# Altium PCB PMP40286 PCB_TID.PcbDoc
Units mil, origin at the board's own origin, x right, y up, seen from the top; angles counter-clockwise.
Board outline 2165.35 x 1574.8 mil, 4 copper layers (Top Layer, Signal Layer 1, Signal Layer 2, Bottom Layer), stack 79.834 mil thick; 40 components, 23 nets, 193 pads, 240 vias.
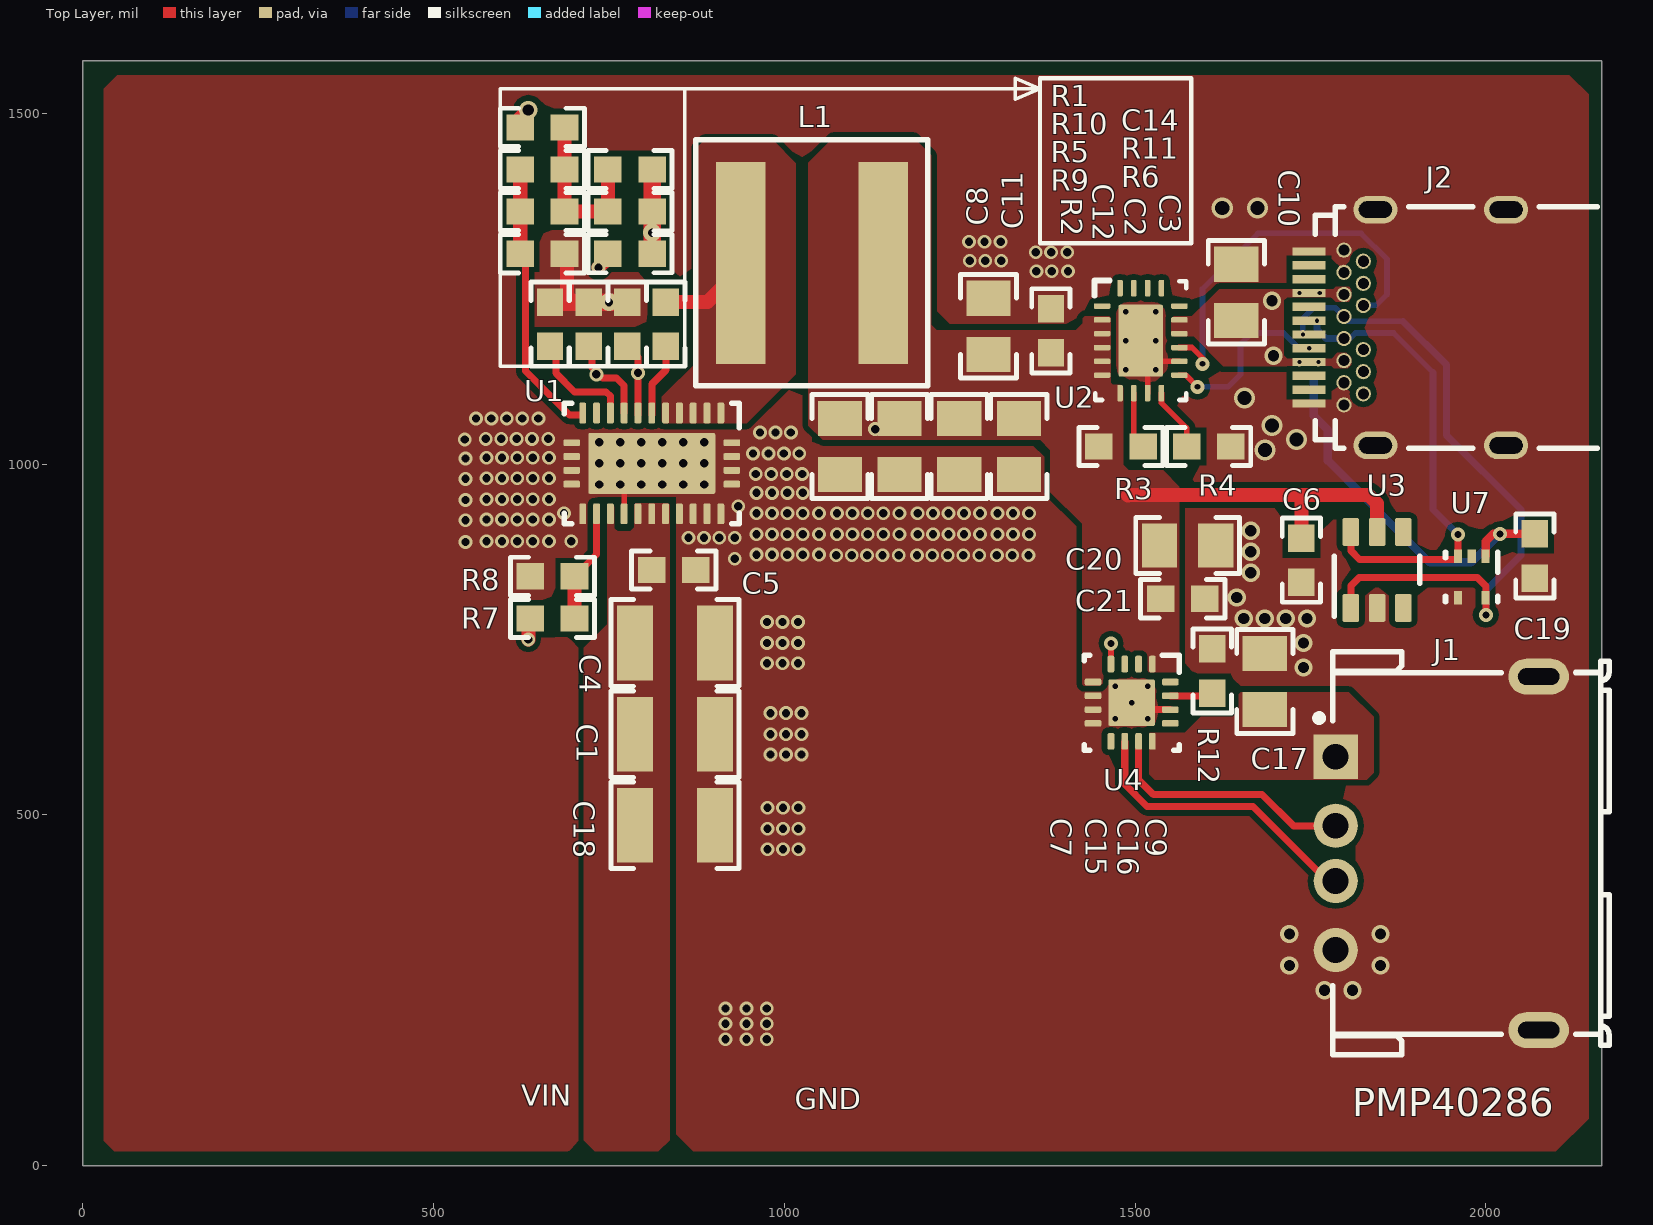
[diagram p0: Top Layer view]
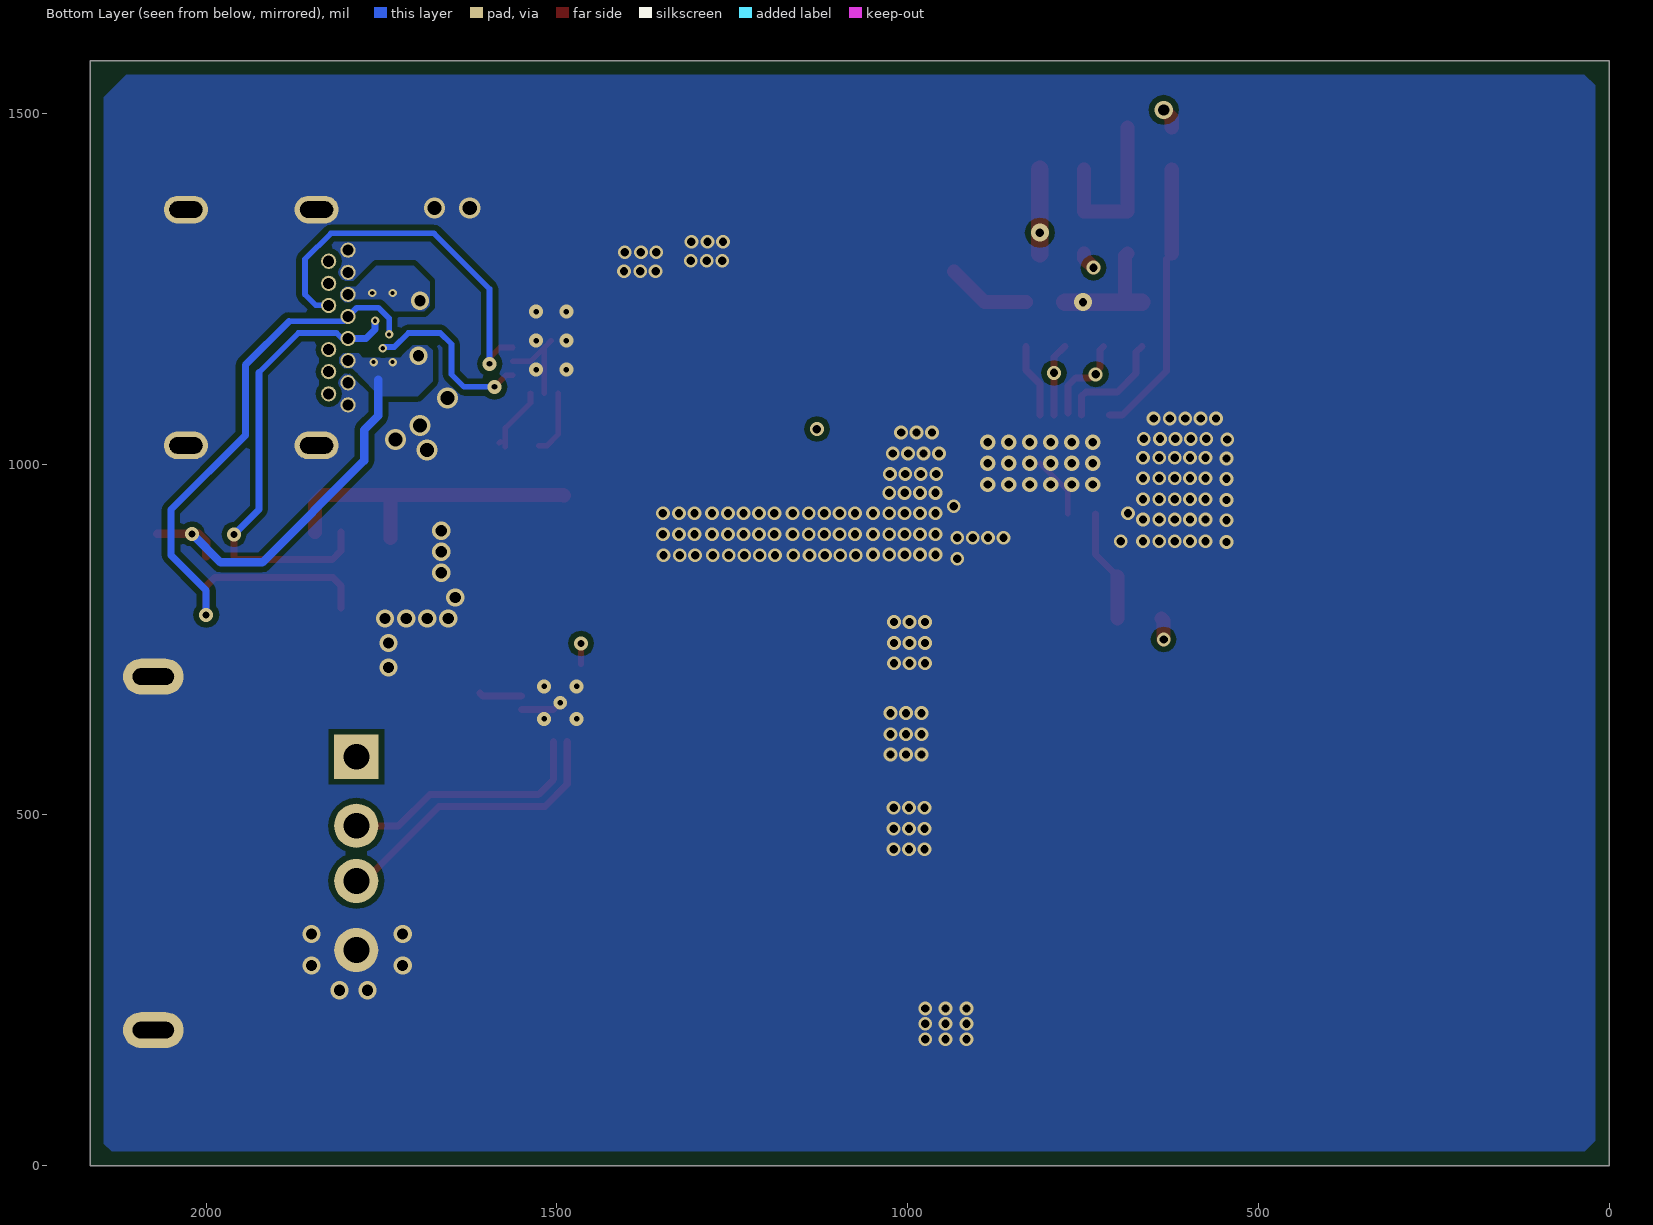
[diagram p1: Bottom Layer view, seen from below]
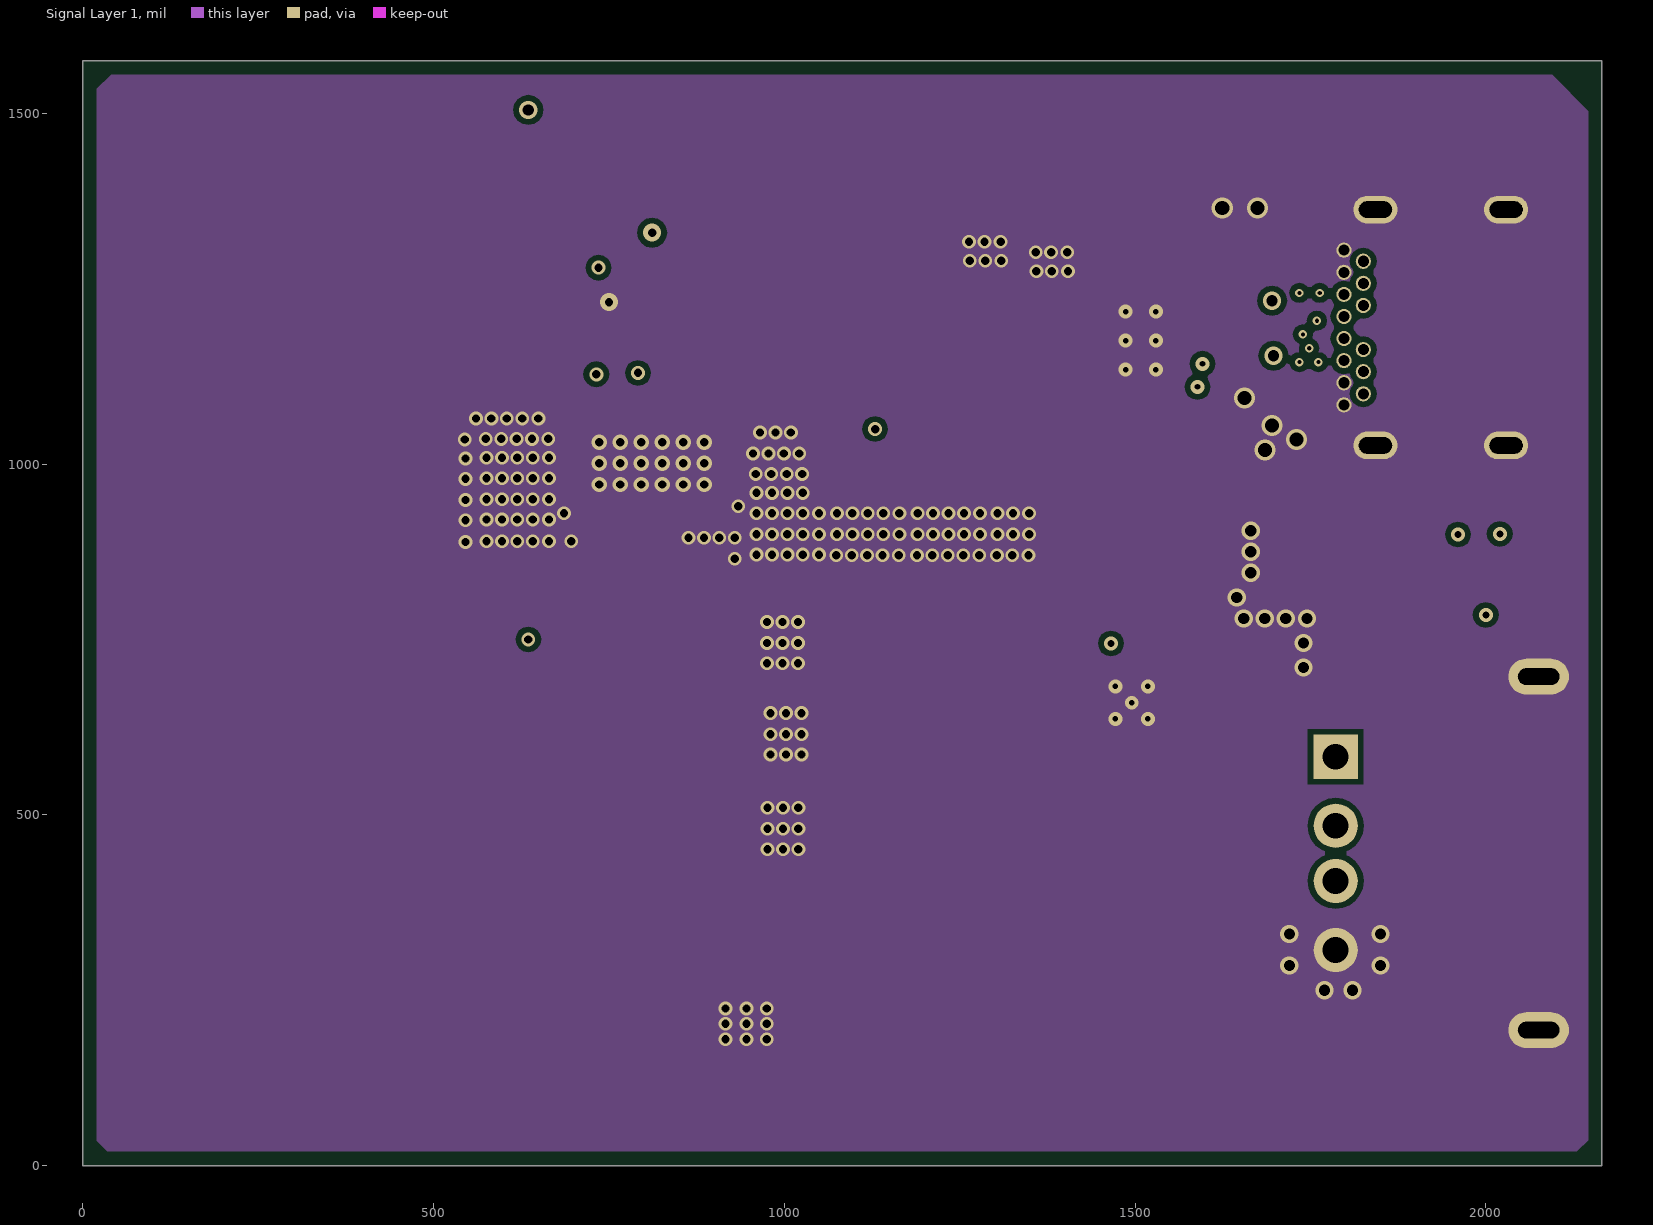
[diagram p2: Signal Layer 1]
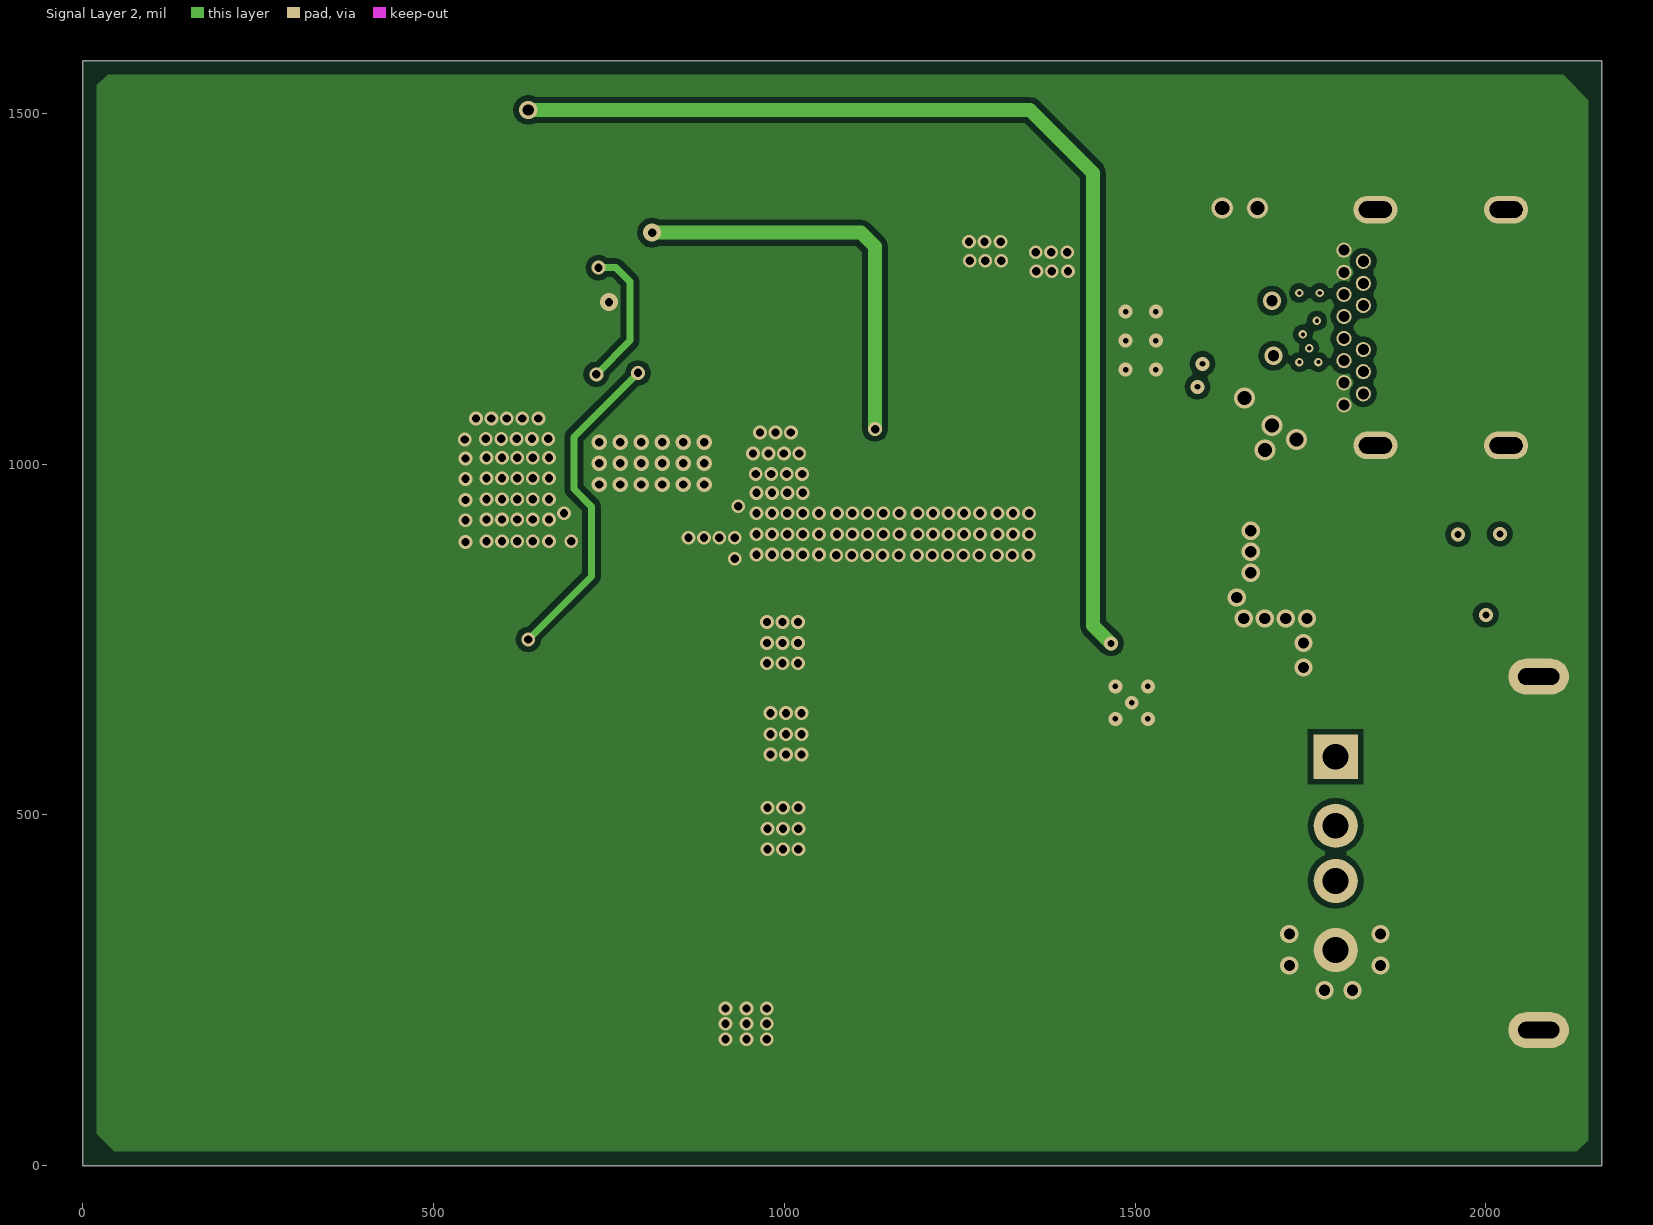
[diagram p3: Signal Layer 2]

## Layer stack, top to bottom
Top Solder: solder mask 0.4, Solder Resist, Dk 3.5
Top Layer: signal copper 1.4
Dielectric1: core 59.2, FR-4, Dk 4.8
Signal Layer 1: signal copper 1.417
Dielectric 3: prepreg 5, Dk 4.2
Signal Layer 2: signal copper 1.417
Dielectric 2: core 10, Dk 4.2
Bottom Layer: signal copper 1.4
Bottom Solder: solder mask 0.4, Solder Resist, Dk 3.5

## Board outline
0,0 2165.35,0 2165.35,1574.8 0,1574.8

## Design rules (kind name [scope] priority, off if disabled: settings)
AcuteAngle [All] p1: minimum=4.50000000000000E+0001 checktracksonly=FALSE
AssemblyTestPointUsage [All] p1: valid=2
Clearance Clearance_BoardEdge_MountingHoles [OnCopper and InComponentClass('Mounting Holes') vs IsKeepOut] p1: gap=40
Clearance Clearance_BoardEdge_Poly [OnCopper and InPoly vs IsKeepOut] p2: gap=5
Clearance Clearance_BoardEdge [OnCopper and Not InComponentClass('Logo') and not InComponentClass('FiducialMark') and not InRegion(1000,500,4000,800) and Not IsKeepout vs IsKeepOut] p3: gap=5
Clearance Clearance_Poly [InPolygon] p4: gap=8
Clearance [All] p5: gap=6
ComponentClearance ComponentClearance_Logo [All] p1: gap=10 collisioncheckmode=3 verticalgap=10 showdistances=TRUE
ComponentClearance ComponentClearance_ScrewToNut [(HasFootprint('NY PMS 440 0025 PH')) vs (HasFootprint('Keystone_1902C'))] p2: gap=5 collisioncheckmode=3 verticalgap=10 showdistances=FALSE
ComponentClearance ComponentClearance_MountingHoles [InComponentClass('Mounting Holes')] p3: gap=10 collisioncheckmode=3 verticalgap=100000 showdistances=FALSE
ComponentClearance ComponentClearance_SmallPassives [HasFootprint('0201*') or HasFootprint('0402*') or HasFootprint('0508') or HasFootprint('0603*') or HasFootprint('0612') or HasFootprint('0805*') or HasFootprint('0815*') or HasFootprint('0830*') or HasFootprint('1206*') or HasFootprint('1210*') or HasFootprint('1808*') or HasFootprint('1812*') or HasFootprint('1825*') or HasFootprint('2010*') or HasFootprint('2220*') or HasFootprint('2225*') or HasFootprint('2512*') or HasFootprint('2728*') or HasFootprint('3518*') vs HasFootprint('0201*') or HasFootprint('0402*') or HasFootprint('0508') or HasFootprint('0603*') or HasFootprint('0612') or HasFootprint('0805*') or HasFootprint('0815*') or HasFootprint('0830*') or HasFootprint('1206*') or HasFootprint('1210*') or HasFootprint('1808*') or HasFootprint('1812*') or HasFootprint('1825*') or HasFootprint('2010*') or HasFootprint('2220*') or HasFootprint('2225*') or HasFootprint('2512*') or HasFootprint('2728*') or HasFootprint('3518*')] p4: gap=10 collisioncheckmode=3 verticalgap=10 showdistances=FALSE
ComponentClearance ComponentClearance_THtoSMT [IsThruComponent vs IsSMTComponent] p5: gap=10 collisioncheckmode=3 verticalgap=100000 showdistances=FALSE
ComponentClearance ComponentClearance_THtoTH [IsThruComponent vs IsThruComponent] p6: gap=10 collisioncheckmode=3 verticalgap=100000 showdistances=FALSE
ComponentClearance [All] p7: gap=10 collisioncheckmode=3 verticalgap=10 showdistances=FALSE
DiffPairsRouting [All] p1: maxlimit=100 minlimit=10 mostfreqgap=10 toplayer_minwidth=15 toplayer_maxwidth=15 toplayer_prefwidth=15 midlayer1_minwidth=15 midlayer1_maxwidth=15 midlayer1_prefwidth=15 midlayer2_minwidth=15 midlayer2_maxwidth=15 midlayer2_prefwidth=15 bottomlayer_minwidth=15 bottomlayer_maxwidth=15 bottomlayer_prefwidth=15 maxuncoupledlength=1000
FabricationTestPointUsage TestPointUsage [All] p1: valid=2 allowmultiple=FALSE
FabricationTestpoint Testpoint [All] p1: side=3 testpointundercomponent=TRUE minsize=40 maxsize=100 preferedsize=60 minholesize=0 maxholesize=40 preferedholesize=32 testpointgrid=1 allowsidetop=TRUE allowsidebottom=TRUE usegrid=TRUE gridtolerance=0.01
FanoutControl Fanout_LCC [IsLCC] p1: bgadir=Out bgaviamode=Centered fanoutstyle=Auto fanoutdirection=Alternating viagrid=1 // Fanout_LCC (Default Rule)
FanoutControl Fanout_BGA [IsBGA] p2: bgadir=Out bgaviamode=Centered fanoutstyle=Auto fanoutdirection=Alternating viagrid=1 // Fanout_BGA (Default Rule)
FanoutControl Fanout_Default [All] p4: bgadir=Out bgaviamode=Centered fanoutstyle=Auto fanoutdirection=Alternating viagrid=1 // Fanout_Default (Default Rule)
FanoutControl Fanout_Small [(CompPinCount < 5)] p5: bgadir=Out bgaviamode=Centered fanoutstyle=Auto fanoutdirection=OutThenIn viagrid=1 // Fanout_Small (Default Rule)
HoleSize [All] p1: absolutevalues=TRUE maxlimit=251 minlimit=6 maxpercent=80.000 minpercent=20.000
MinimumAnnularRing [All] p1: minimumring=3
MinimumSolderMaskSliver MinimumSolderMaskSliver_Logo [InComponentClass('Logo') vs InComponentClass('Logo')] p1: minsoldermaskwidth=0.7
MinimumSolderMaskSliver [All] p2: minsoldermaskwidth=0
PlaneConnect [All] p1: planeconnectstyle=Direct reliefexpansion=10 reliefentries=4 reliefconductorwidth=10 reliefairgap=10
PolygonConnect [All] p1: connectstyle=Direct reliefconductorwidth=10 reliefentries=4 polygonreliefangle="90 Angle" airgapwidth=10
RoutingCorners [All] p1: cornerstyle=45-Degree minsetback=10 maxsetback=100
RoutingVias [All] p1: holewidth=16 width=34 viastyle="Through Hole" minholewidth=8 minwidth=16 maxholewidth=40 maxwidth=65
SMDToCorner [All] p1: distance=0
SilkToBoardRegionClearance [Not ((IsComment or IsDesignator) And (Hide <> 'False')) and not InRegion(1000,500,4000,800)] p1:
SilkToSilkClearance [All] p1: silktosilkclearance=0
SilkToSolderMaskClearance SilkscreenOverComponentPads [IsPad] p1: minsilkscreentomaskgap=0 clearancetoexposedcopper=TRUE
SolderMaskExpansion [All] p1: expansion=3
Width [All] p1: maxlimit=100 minlimit=6 preferedwidth=10 checkconnectedcopper=TRUE
14 further rules are at their usual default settings.

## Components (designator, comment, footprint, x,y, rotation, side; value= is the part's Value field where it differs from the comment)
C1 "GRM32ER71H106KA12L" 1210 844.33,614.96 r0 top
C2 "GRM188R61A225KE34D" 0603 775.99,1199.43 r90 top
C3 "GRM188R71A474KA61D" 0603 830.99,1199.43 r90 top
C4 "GRM32ER71H106KA12L" 1210 844.33,744.96 r0 top
C5 "C1608X7R1H474K080AC" 0603 842.33,848.96 r0 top
C6 "06033C104JAT2A" 0603 1737,863 r270 top
C7 "GRM21BR61A476ME15" 0805_HV 1079.33,1024.96 r270 top
C8 "GRM21BR61A476ME15" 0805_HV 1291.11,1196.47 r90 top
C9 "GRM21BR61A476ME15" 0805_HV 1334.33,1024.96 r270 top
C10 "C0805C106K8PACTU" 0805_HV 1644.33,1244.96 r90 top
C11 "C1608X7R1E104K" 0603 1380,1190 r90 top
C12 "C1608X7R1E104K" 0603 720.99,1199.43 r90 top
C14 "C0603C223K5RACTU" 0603 780,1420 r180 top
C15 "GRM21BR61A476ME15" 0805_HV 1164.33,1024.96 r270 top
C16 "GRM21BR61A476ME15" 0805_HV 1249.33,1024.96 r270 top
C17 "GRM219R61A106KE44D" 0805_HV 1685,690 r90 top
C18 "GRM32ER71H106KA12L" 1210 844.33,484.96 r0 top
C19 "06033C104JAT2A" 0603 2070,869 r270 top
C20 "C0805C106K8PACTU" 0805_HV 1575,884 r0 top
C21 "C1608X7R1E104K" 0603 1568,808 r0 top
J1 "614 104 150 121" WURTH_614104150121 1786.05,445.01 r90 top
J2 "632 723 300 011" Wurth_632_723_300_011 2164.76,1194.72 r90 top
L1 "XAL8080-682MEB" XAL8080 1039.33,1286.96 r0 top
R1 "RC0603JR-070RL" 0603 655,1480 r0 top
R2 "" 0603 665.99,1199.43 r270 top
R3 "CRCW060310K0JNEA" 0603 1480,1025 r180 top
R4 "RC0603FR-07100KL" 0603 1605,1025 r180 top
R5 "RC0603FR-0747KL" 0603 655,1360 r0 top
R6 "CRCW06033R00JNEA" 0603 780,1300 r0 top
R7 "CRCW06030000Z0EA" 0603 669.33,779.96 r180 top
R8 "CRCW06030000Z0EA" 0603 669.33,839.96 r180 top
R9 "CRCW060310K0FKEA" 0603 655,1300 r180 top
R10 "RC0603FR-07200KL" 0603 655,1420 r0 top
R11 "RC0603FR-072K1L" 0603 780,1360 r180 top
R12 "RT0603BRD0720KL" 0603 1610,705 r270 top
U1 "LM73606RNPR" RNP0030A 810.99,1000.93 r270 top
U2 "TPS25810-Q1" RVC0020A 1508.1,1176.02 r0 top
U3 "TPS2514AQDBVRQ1" DBV0006A_N 1845,849 r90 top
U4 "TPS2549IRTERQ1" RTE0016C 1495.16,659.84 r270 top
U7 "TPD2E001IDRLRQ1" DRL0005A 1980,839 r270 top

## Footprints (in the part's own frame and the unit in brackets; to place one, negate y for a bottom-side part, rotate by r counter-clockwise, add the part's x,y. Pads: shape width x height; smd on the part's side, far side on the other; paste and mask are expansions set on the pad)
0603 [mm] "0603 from SM-752 data"
  rect 1x0.95 smd: 1(-0.8,0) 2(0.8,0)
  silkscreen extent -1.52,-0.69 1.52,0.69, body extent -0.87,-0.47 0.87,0.47, height 1
0805_HV [mil] "0805 with 30mil clearance between pads"
  rect 50x63 smd: 1(-40,0) 2(40,0)
  silkscreen extent -74,-40 74,40, body extent -43,-29 43,29, height 57
1210 [mm] "1210 from SM-752 data"
  rect 1.3x2.7 smd: 1(-1.45,0) 2(1.45,0)
  silkscreen extent -2.32,-1.57 2.32,1.57, body extent -1.7,-1.35 1.7,1.35, height 1.35
DBV0006A_N [mm] "SOT23, 6-Leads, Body 2.9x1.6mm, Pitch 0.95mm, Lead Span 2.8mm, IPC Medium Density"
  rrect17% 1x0.6 smd: 1(-1.375,0.95) 2(-1.375,0) 3(-1.375,-0.95) 4(1.375,-0.95) 5(1.375,0) 6(1.375,0.95)
  silkscreen extent -1.68,-1.55 0.5,1.55, body extent -1.42,-1.46 1.42,1.46, height 1.12
DRL0005A [mm] "SOTFL, 5-Flat Leads, Body 1.2x1.6x0.6mm, Pitch 0.5mm, TI recommended"
  rect 0.5x0.3 smd: 1(-0.75,0.5) 2(-0.75,0) 3(-0.75,-0.5) 4(0.75,-0.5) 5(0.75,0.5)
  silkscreen extent -0.9,-0.95 0.9,0.95, body extent -0.85,-0.85 0.85,0.85, height 0.62
RNP0030A [mm] "QFN, 30-Leads, Body 6x4mm, Pitch 0.5mm, Thermal Pad 4.6x2.2mm"
  rrect40% 0.75x0.25 smd: 1(-1.825,2.5) 2(-1.825,2) 3(-1.825,1.5) 4(-1.825,1) 5(-1.825,0.5) 6(-1.825,0) 7(-1.825,-0.5) 8(-1.825,-1) 9(-1.825,-1.5) 10(-1.825,-2) 11(-1.825,-2.5) 16(1.825,-2.5) 17(1.825,-2) 18(1.825,-1.5) 19(1.825,-1) 20(1.825,-0.5) 21(1.825,0) 22(1.825,0.5) 23(1.825,1) 24(1.825,1.5) 25(1.825,2) 26(1.825,2.5)
  rrect40% 0.25x0.6 smd: 12(-0.75,-2.9) 13(-0.25,-2.9) 14(0.25,-2.9) 15(0.75,-2.9) 27(0.75,2.9) 28(0.25,2.9) 29(-0.25,2.9) 30(-0.75,2.9)
  rrect5% 2.2x4.6 smd paste-3: 31(0,0)
  rrect50% 0.98x0.96 on Top Paste: 31A(-0.59,1.74) 31A(-0.59,0.58) 31A(-0.59,-0.58) 31A(-0.59,-1.74) 31A(0.59,1.74) 31A(0.59,0.58) 31A(0.59,-0.58) 31A(0.59,-1.74)
  silkscreen extent -2.17,-3.18 2.17,3.18, body extent -2.07,-3.07 2.07,3.07, height 0.81
RTE0016C [mm] "Texas Insturments"
  rrect42% 0.6x0.24 smd: 1(-1.4,0.75) 2(-1.4,0.25) 3(-1.4,-0.25) 4(-1.4,-0.75) 9(1.4,-0.75) 10(1.4,-0.25) 11(1.4,0.25) 12(1.4,0.75)
  rrect42% 0.24x0.6 smd: 5(-0.75,-1.4) 6(-0.25,-1.4) 7(0.25,-1.4) 8(0.75,-1.4) 13(0.75,1.4) 14(0.25,1.4) 15(-0.25,1.4) 16(-0.75,1.4)
  rrect6% 1.55x1.55 on Top Paste: 17(0,0)
  rrect6% 1.68x1.68 smd paste-0.85: 17(0,0)
  silkscreen extent -1.72,-1.73 1.72,1.73, body extent -1.57,-1.57 1.58,1.58, height 0.81
RVC0020A [mm] "TI"
  rrect50% 0.6x0.2 smd: 1(-1.4,1.25) 2(-1.4,0.75) 3(-1.4,0.25) 4(-1.4,-0.25) 5(-1.4,-0.75) 6(-1.4,-1.25) 11(1.4,-1.25) 12(1.4,-0.75) 13(1.4,-0.25) 14(1.4,0.25) 15(1.4,0.75) 16(1.4,1.25)
  rrect50% 0.2x0.6 smd: 7(-0.75,-1.9) 8(-0.25,-1.9) 9(0.25,-1.9) 10(0.75,-1.9) 17(0.75,1.9) 18(0.25,1.9) 19(-0.25,1.9) 20(-0.75,1.9)
  rrect9% 1.47x1.15 on Top Paste: 21(0,-0.675) 21(0,0.675)
  rrect6% 1.6x2.6 smd paste-1: 21(0,0)
  silkscreen extent -1.68,-2.15 1.65,2.18, body extent -1.55,-2.05 1.55,2.05, height 0.8
Wurth_632_723_300_011 [mm] "Connector, Receptacle, USB Type C, R/A"
  rect 0.3x1.2 smd: A1(-2.75,10.58) A2(-2.25,10.58) A3(-1.75,10.58) A4(-1.25,10.58) A5(-0.75,10.58) A6(-0.25,10.58) A7(0.25,10.58) A8(0.75,10.58) A9(1.25,10.58) A10(1.75,10.58) A11(2.25,10.58) A12(2.75,10.58)
  round 0.55 hole 0.4: B1(2.8,9.32) B2(2.4,8.62) B3(1.6,8.62) B4(1.2,9.32) B5(0.8,8.62) B6(0.4,9.32) B7(-0.4,9.32) B8(-0.8,8.62) B9(-1.2,9.32) B10(-1.6,8.62) B11(-2.4,8.62) B12(-2.8,9.32) M1(2,9.32) M2(-2,9.32)
  rrect100% 1x1.6 hole 0.6 slot 1.2 at 90 deg: S1(-4.27,8.18) S2(-4.27,3.45) S3(4.27,3.45) S4(4.27,8.18)
  silkscreen extent -4.37,0.15 4.37,10.36, body extent -4.37,-0.96 4.37,10.83, height 3.07
WURTH_614104150121 [mm] "USB2.0 A, TH"
  rect 1.6x1.6 hole 0.94: 1(3.5,0)
  round 1.6 hole 0.94: 2(1,0) 3(-1,0) 4(-3.5,0)
  oval 1.3x2.2 hole 0.6 slot 1.5 at 90 deg: 5(-6.4,-7.35) 6(6.4,-7.35)
  silkscreen extent -7.3,-9.9 7.3,0.72, body extent -7.3,-9.9 7.3,0.1, height 6.93
XAL8080 [mm] "Coilcraft"
  rect 1.78x7.31 smd: 1(-2.58,0) 2(2.58,0)
  silkscreen extent -4.2,-4.45 4.2,4.45, body extent -4.15,-4.4 4.15,4.4, height 8

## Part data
C1 C4 C18: "CAP, CERM, 10 µF, 50 V, +/- 10%, X7R, 1210"
C2: "CAP, CERM, 2.2 µF, 10 V, +/- 10%, X5R, 0603"
C3: "CAP, CERM, 0.47 µF, 10 V, +/- 10%, X7R, 0603"
C5: "CAP, CERM, 0.47 µF, 50 V, +/- 10%, X7R, 0603"
C6 C19: "CAP, CERM, 0.1 µF, 25 V, +/- 5%, X7R, 0603"
C7 C8 C9 C15 C16: "CAP, CERM, 47 µF, 10 V, +/- 20%, X5R, 0805"
C10 C17 C20: "CAP, CERM, 10 µF, 10 V, +/- 10%, X5R, 0805"
C11 C12 C21: "CAP, CERM, 0.1 µF, 25 V, +/- 10%, X7R, 0603"
C14: "CAP, CERM, 0.022 µF, 50 V, +/- 10%, X7R, 0603"
J1: "Connector, Receptacle, USB Type A, R/A, Bottom Mount TH"
J2: "Connector, Receptacle, USB Type C, R/A"
L1: library part XAL8080-682meb, "Inductor, Shielded, Composite, 6.8 µH, 11.3 A, 0.0132 ohm, SMD"
R1 R7 R8: "RES, 0, 5%, 0.1 W, 0603"
R2: library part RT0603BRD0719K1L, "RES, 112k, 1%, 0.1 W, 0603"
R3: "RES, 10 k, 5%, 0.1 W, 0603"
R4: "RES, 100 k, 1%, 0.1 W, 0603"
R5: "RES, 47.0 k, 1%, 0.1 W, 0603"
R6: "RES, 3.0, 5%, 0.1 W, 0603"
R9: "RES, 10.0 k, 1%, 0.1 W, 0603"
R10: "RES, 200 k, 1%, 0.1 W, 0603"
R11: "RES, 2.10 k, 1%, 0.1 W, 0603"
R12: "RES, 20.0 k, 0.1%, 0.1 W, 0603"
U1: library part LM73605RNPR, "3.5V to 36V 5A Synchronous Step-Down Voltage Regulator, RNP0030A"
U2: library part TPS25810RVC, "USB Type-C DFP Controller and Power Switch with Load Detection, RVC0020A"
U3: library part TPS2514ADBV, "USB Dedicated Charging Port Controller, DBV0006A"
U4: "USB Charging Port Controller, RTE0016C (WQFN-16)"
U7: library part TPD2E001DRLRG4, "Low-Capacitance + / - 15 kV ESD-Protection Array for High-Speed Data Interfaces, 2 Channels, 5-pin SOT (DRL), Green (RoHS & no Sb/Br)"

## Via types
v1: diameter 19.68, hole 11.81, Top Layer to Bottom Layer, 167 vias
v2: diameter 26, hole 16, Top Layer to Bottom Layer, 19 vias
v3: diameter 22, hole 12, Top Layer to Bottom Layer, 18 vias
v4: diameter 19.68, hole 7.87, Top Layer to Bottom Layer, 11 vias
v5: diameter 12, hole 6, Top Layer to Bottom Layer, 7 vias
v6: diameter 30, hole 20, Top Layer to Bottom Layer, 6 vias
v7: diameter 20, hole 12, Top Layer to Bottom Layer, 4 vias
v8: diameter 20, hole 10, Top Layer to Bottom Layer, 2 vias
v9: diameter 20/20/20/20 (per signal layer), hole 10, Top Layer to Bottom Layer, 2 vias
v10: diameter 26, hole 12, Top Layer to Bottom Layer, 2 vias
v11: diameter 20, hole 8, Top Layer to Bottom Layer, 2 vias

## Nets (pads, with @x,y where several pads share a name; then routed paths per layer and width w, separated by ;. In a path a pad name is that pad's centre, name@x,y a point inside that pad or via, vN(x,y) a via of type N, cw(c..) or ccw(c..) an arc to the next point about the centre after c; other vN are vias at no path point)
B_D+: J1.3 U4.10 | length 419
  Top Layer w10: U4.10 1485.32,543.68 1517,512 1668,512 1774.36,405.64 J1.3
B_D-: J1.2 U4.11 | length 363
  Top Layer w10: U4.11 1505,550 1526,529 1681,529 1725.62,484.38 J1.2
B_VBUS: C17.1 J1.1 U4.12
CC1_2: J2.A5 U2.11 | length 258
  Top Layer w8: U2.11 1572.31,1126.81 v11(1589.1,1110.02)
  Bottom Layer w8: v11(1589.1,1110.02) 1632.39,1110.02 1650.33,1127.96 1650.33,1170.96 1666.33,1186.96 1711.87,1186.96 1731.87,1166.96 1746.46,1166.96 v5(1748.22,1165.2)
CC2_2: J2.B5 U2.13 | length 555.5
  Top Layer w8: U2.13 1580.94,1166.18 1596.1,1151.02 v11(1596.1,1143.02)
  Bottom Layer w8: v11(1596.1,1143.02) 1596.1,1249.73 1675.33,1328.96 1822.33,1328.96 1859.11,1292.18 1859.11,1241.74 1843.59,1226.22 J2.B5
CS: C14.2 R1.2 R5.2 R10.2 R11.2 | length 242
  Top Layer w20: R1.2 R10.2 R5.2 R11.2 C14.2
D+2: J2.A6 J2.B6 U3.1 U7.5 | length 963.2
  Top Layer w10: U3.1 1807.6,826.6 1819,838 1988,838 2000,826 v9(2000,785)
  Bottom Layer w8: v5(1739.33,1184.96) 1739.33,1207.96 1754.33,1222.96 1785.34,1222.96 J2.B6 J2.B6@1803.91,1204.39 ; J2.B6@1803.91,1203.39 1882.19,1203.39
  Bottom Layer w10: 1882.19,1203.39 1944.33,1141.25 1944.33,1040.67 2050,935 2050,870 2000,820 v9(2000,785)
D-2: J2.A7 J2.B7 U3.6 U7.3 | length 665.9
  Top Layer w10: U3.6 1807.6,876.4 1820,864 U7.3@1954.79,864 ; U7.3 v9(1960.32,899.68)
  Bottom Layer w8: J2.B7 1806.35,1178.98 1814.33,1186.96 1868.62,1186.96 1925,1130.58
  Bottom Layer w10: v5(1759.33,1204.46) 1759.33,1191.96 1772.31,1178.98 J2.B7 ; 1925,1130.58 1925,935 v9(1960.32,899.68)
FB: R5.1 R9.2 R10.1 U1.11 | length 398.1
  Top Layer w10: R9.2 630.99,1292.52 630.99,1132.64 693.85,1069.78 U1.11@712.56,1069.78
  Top Layer w20: R9.2 R10.1
GND: C1.2 C2.2 C4.2 C5.2 C6.2 C7.2 C8.2 C9.2 C10.2 C11.2 C12.2 C15.2 C16.2 C17.2 C18.2 C19.2 C20.2 C21.2 J1.4 J1.5 J1.6 J2.A1 J2.A12 J2.B1 J2.B12 J2.M1 J2.M2 J2.S1 J2.S2 J2.S3 J2.S4 R2.1 R4.1 R8.2 R9.1 R12.1 U1.12 U1.13 U1.14 U1.15 U1.16 U1.19 U1.23 U1.24 U1.25 U1.26 U1.27 U1.28 U1.29 U1.30 U1.31 U2.9 U2.12 U2.21@1508.1,1176.02 U3.2 U4.6 U4.7 U4.8 U4.14 U4.17@1495.16,659.84 U7.4 | length 460.2
  Top Layer w8: U1.19 771.62,961.56 U1.31 ; U2.21@1508.1,1176.02 U2.21@1517.94,1166.18 ; U2.9 U2.21@1517.94,1166.18 ; U2.12 1537.63,1146.5 U2.21@1517.94,1166.18
  Top Layer w10: v4(1495.16,659.84) 1505,650 U4.14
  Top Layer w20: R9.1 690,1296.5 690,1230.92
  Top Layer w25: R2.1 690,1230.92 C12.2 v10(750,1230.92) C2.2
  other v1: 916,180 946,180 975,180 916,202 946,202 975,202 916,224 946,224 975,224 976,451 998,451 1020,451 976,480 998,480 1020,480 976,510 998,510 1020,510 980.33,585.96 1002.33,585.96 1024.33,585.96 980.33,614.96 1002.33,614.96 1024.33,614.96 980.33,644.96 1002.33,644.96 1024.33,644.96 975.33,715.96 997.33,715.96 1019.33,715.96 975.33,744.96 997.33,744.96 1019.33,744.96 975.33,774.96 997.33,774.96 1019.33,774.96 929.33,864.96 1074,870 1096,870 1118,870 1140,870 1163,870 1189,870 1211,870 1233,870 1255,870 1278,870 1303,870 1325,870 1348,870 960.33,870.96 982.33,870.96 1004.33,870.96 1026.33,870.96 1049.33,870.96 545.33,888.96 575.33,889.96 597.33,889.96 619.33,889.96 641.33,889.96 664.33,889.96 696.33,889.96 863.33,894.96 885.33,894.96 907.33,894.96 929.33,894.96 960.33,899.96 982.33,899.96 1004.33,899.96 1026.33,899.96 1049.33,899.96 1075,900 1097,900 1119,900 1141,900 1164,900 1190,900 1212,900 1234,900 1256,900 1279,900 1304,900 1326,900 1349,900 545.33,919.96 575.33,920.96 597.33,920.96 619.33,920.96 641.33,920.96 664.33,920.96 685.99,930.06 960.33,929.96 982.33,929.96 1004.33,929.96 1026.33,929.96 1049.33,929.96 1075,930 1097,930 1119,930 1141,930 1164,930 1190,930 1212,930 1234,930 1256,930 1279,930 1304,930 1326,930 1349,930 934.33,939.96 545.33,948.96 575.33,949.96 597.33,949.96 619.33,949.96 641.33,949.96 664.33,949.96 960.33,958.96 982.33,958.96 1004.33,958.96 1026.33,958.96 545.33,978.96 575.33,979.96 597.33,979.96 619.33,979.96 641.33,979.96 664.33,979.96 959.33,985.96 981.33,985.96 1003.33,985.96 1025.33,985.96 545.33,1007.96 575.33,1008.96 597.33,1008.96 619.33,1008.96 641.33,1008.96 664.33,1008.96 955.33,1014.96 977.33,1014.96 999.33,1014.96 1021.33,1014.96 544.33,1034.96 574.33,1035.96 596.33,1035.96 618.33,1035.96 640.33,1035.96 663.33,1035.96 965.33,1044.96 987.33,1044.96 1009.33,1044.96 560.33,1064.96 582.33,1064.96 604.33,1064.96 626.33,1064.96 649.33,1064.96 1359.33,1274.96 1381.33,1274.96 1404.33,1274.96 1264.33,1289.96 1286.33,1289.96 1309.33,1289.96 1358.33,1301.96 1380.33,1301.96 1403.33,1301.96 1263.33,1316.96 1285.33,1316.96 1308.33,1316.96
  other v2: 1770,250 1810,250 1720,285 1850,285 1720,330 1850,330 1740,710 1740,745 1655,780 1685,780 1715,780 1745,780 1645,810 1665,845 1665,875 1665,905
  other v3: 735.99,970.93 765.99,970.93 795.99,970.93 825.99,970.93 855.99,970.93 885.99,970.93 735.99,1000.93 765.99,1000.93 795.99,1000.93 825.99,1000.93 855.99,1000.93 885.99,1000.93 735.99,1030.93 765.99,1030.93 795.99,1030.93 825.99,1030.93 855.99,1030.93 885.99,1030.93
  other v4: 1471.93,636.61 1518.39,636.61 1471.93,683.07 1518.39,683.07 1486.45,1134.68 1529.75,1134.68 1486.45,1176.02 1529.75,1176.02 1486.45,1217.36 1529.75,1217.36
  other v6: 1685,1020 1730,1035 1695,1055 1656.33,1093.96 1624.33,1364.96 1674.33,1364.96
NetC2_1: C2.1 R7.2 U1.7 | length 601.1
  Top Layer w10: C2.1 791.3,1152.61 v7(791.3,1129.96) U1.7 U1.7@791.3,1069.78
  Top Layer w20: v1(635,750) 635,777.2 R7.2 R7.2
  Signal Layer 2 w10: v1(635,750) 725,840 725,939.27 700,964.27 700,1038.66 v7(791.3,1129.96)
NetC3_1: C3.1 U1.6 | length 106.4
  Top Layer w10: U1.6@810.99,1069.78 U1.6 810.99,1113.85 830.99,1133.85 C3.1
NetC12_1: C12.1 R6.1 U1.8 | length 337.5
  Top Layer w10: C12.1 725.99,1162.93 725.99,1137.93 ; 740.99,1122.93 760.99,1122.93 771.62,1112.3 U1.8
  Top Layer w20: v7(735,1280) 748.5,1293.5 R6.1
  Signal Layer 2 w10: v7(731.99,1127.93) 780,1175.94 780,1260 760,1280 v7(735,1280)
NetR1_1: R1.1 U4.4 | length 1582.7
  Top Layer w8: U4.4 v8(1465.63,744.37)
  Top Layer w20: R1.1 623.5,1493.5 v2(635,1505)
  Signal Layer 2 w20: v2(635,1505) 1350,1505 1440,1415 1440,770 v8(1465.63,744.37)
NetR2_2: R2.2 U1.9 | length 160.1
  Top Layer w10: R2.2 674.33,1159.59 674.33,1129.59 700.99,1102.93 745.99,1102.93 751.93,1096.98 U1.9@751.93,1069.78
NetR3_1: R3.1 U2.8 | length 93.5
  Top Layer w8: U2.8 1498.26,1042.33 1514.56,1026.02 R3.1@1526.09,1026.02
NetR4_2: R4.2 U2.10 | length 93.3
  Top Layer w8: U2.10 1537.63,1087.37 1573.5,1051.5 R4.2 ; R4.2@1580.55,1032.04 R4.2@1582.12,1030.47
NetR7_1: R7.1 R8.1 U1.17 | length 162.1
  Top Layer w10: R8.1 732.25,871.38 U1.17
  Top Layer w20: R7.1 R8.1
NetR12_2: R12.2 U4.15 | length 61.3
  Top Layer w10: U4.15 1606.18,669.69 R12.2
SW: C3.2 L1.1 U1.1 U1.2 U1.3 U1.4 U1.5 | length 121.1
  Top Layer w20: C3.2 890.14,1230.92 L1.1@933.94,1274.72
VBUS2: C10.1 C19.1 J2.A4 J2.A9 J2.B4 J2.B9 U2.14 U2.15 U7.1 | length 541.1
  Top Layer w12: U7.1 1999.69,889.69 2010.5,900.5 v8(2020,900.5) C19.1
  Bottom Layer w12: 1755,1120 1755,1068.66 1775,1048.66 1775,1005 1920,860 1979.5,860 v8(2020,900.5)
  other v2: 1697.32,1154.51 1695.33,1232.96
  other v5: 1734.33,1145.46 1761.33,1145.46 1734.32,1243.96 1763.32,1243.96
VIN: C1.1 C4.1 C5.1 C18.1 U1.18 U1.20 U1.21 U1.22
VOUT: C6.1 C7.1 C8.1 C9.1 C11.1 C14.1 C15.1 C16.1 C20.1 C21.1 L1.2 R3.2 R6.2 R11.1 U2.2 U2.3 U2.4 U2.5 U2.6 U2.7 U3.5 U4.1 U4.5 | length 1169.7
  Top Layer w20: 1490,955 1491,956 1735,956 ; C6.1 1737,954 1735,956 ; U3.5 1845,944 1833,956 1735,956
  Top Layer w25: R6.2 v10(811.5,1330) C14.1
  Signal Layer 2 w20: v10(811.5,1330) 1109.29,1330 1129.33,1309.96 v7(1129.33,1049.96)
pads on no net: J2.A2 J2.A3 J2.A8 J2.A10 J2.A11 J2.B2 J2.B3 J2.B8 J2.B10 J2.B11 U1.10 U1.31A U2.1 U2.16 U2.17 U2.18 U2.19 U2.20 U2.21@1508.1,1149.45 U2.21@1508.1,1202.6 U3.3 U3.4 U4.2 U4.3 U4.9 U4.13 U4.16 U4.17@1495.16,659.84 U7.2

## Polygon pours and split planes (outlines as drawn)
VOUT on Top Layer "Top Layer-No Net 2" (solid, pour order 1): 1069.55,1464.96 1184.68,1464.96 1209.33,1440.31 1209.33,1198.96 1217.33,1190.96 1415.33,1190.96 1425.33,1200.96 1425.33,1207.96 1428.33,1210.96 1463.33,1210.96 1465.33,1208.96 1465.33,1115.96 1468.33,1112.96 1481.33,1112.96 1483.33,1110.96 1483.33,998.96 1491.33,990.96 1540.04,990.96 1562.96,968.04 1562.96,767.96 1562.96,707.96 1558,703 1484.67,703 1455,703 1455,685 1454,684 1427,684 1425,686 1425,905 1425,915 1379.33,959.96 1379.33,1019.96 1364.91,1034.38 1299.33,1034.38 1239.91,1034.38 1054.91,1034.38 1034.33,1054.96 1034.33,1429.75
VIN on Top Layer "Top Layer-No Net 3" (solid, pour order 0): 747.33,942.6 757.41,942.6 757.41,908.88 762.33,903.96 780.33,903.96 786.33,909.96 786.33,941.96 788.33,943.96 834.33,943.96 836.33,941.96 836.33,36.33 820,20 730,20 714,36 714,738 747.33,771.33
SW on Top Layer "Top Layer-No Net" (solid, pour order 2): 828.46,1057.96 825.49,1060.93 825.49,1095.93 876.49,1146.93 876.49,1452.12 886.53,1462.16 983.13,1462.16 1016.33,1428.96 1016.33,1127.96 946.33,1057.96
VBUS2 on Top Layer "Top Layer-No Net 1" (solid, remove dead copper, pour order 52): 1551.33,1207.96 1554.33,1210.96 1580.89,1210.96 1620.18,1249.51 1782.32,1249.51 1785.82,1253.01 1806.32,1253.01 1808.32,1249.51 1808.32,1237.51 1804.32,1231.51 1786.32,1231.51 1780.32,1237.51 1716.32,1237.51 1712.32,1233.51 1712.32,1155.51 1717.32,1150.51 1780.32,1150.51 1788.32,1158.51 1801.32,1158.51 1808.32,1151.51 1808.32,1141.51 1803.32,1136.51 1783.32,1136.51 1780.32,1139.51 1703.32,1139.51 1625.78,1139.51 1583.33,1181.96 1556.59,1181.96 1551.33,1181.96
B_VBUS on Top Layer "Top Layer-No Net 4" (solid, pour order 72): 1520,616 1521,617 1570,617 1571,617 1590,636 1594,640 1637,640 1639,640 1645,646 1648,649 1648,672 1651,675 1805,675 1840,640 1840,560 1830,550 1723,550 1528,550 1520,558
GND on Top Layer "Top Layer-No Net 4" (solid, pour order 74): 30,1535 49.12,1554.12 1008.09,1554.12 2119.33,1554.12 2146.51,1526.94 2146.51,66.51 2100,20 870,20 845.65,44.35 845.65,953.75 737.65,953.75 737.65,59.65 695,20 45,20 30,35
GND on Bottom Layer "Signal Layer 2-No Net" (solid, remove dead copper, pour order 68): 20,1540 35.12,1555.12 2114.17,1555.12 2146.33,1522.96 2146.33,31.33 2135,20 35,20 20,35
VBUS2 on Bottom Layer "Bottom Layer-No Net 1" (solid, pour order 22): 1681.34,1259.87 1704.34,1282.87 1757.34,1282.87 1774.65,1265.55 1787.19,1253.01 1801.65,1253.02 1808.65,1246.01 1808.65,1237.01 1802.65,1231.02 1777.65,1231.01 1773.49,1231.01 1760.34,1217.87 1689.34,1217.87 1681.34,1225.87
VBUS2 on Bottom Layer "Bottom Layer-No Net 2" (solid, pour order 24): 1684.58,1169.43 1705.84,1169.43 1717.55,1157.72 1723.55,1151.72 1776.52,1151.72 1782.52,1157.72 1804.52,1157.72 1810.52,1151.72 1810.52,1143.72 1803.52,1136.72 1792.09,1136.72 1752.33,1096.96 1698.31,1096.96 1677.21,1118.06 1677.21,1162.06
GND on Signal Layer 1 "Signal Layer 2-No Net" (solid, pour order 64): 20,1535 40.12,1555.12 2094.49,1555.12 2146.33,1503.28 2146.33,36.33 2130,20 35,20 20,35
GND on Signal Layer 2 "Signal Layer 2-No Net" (solid, pour order 66): 20,1540 35.12,1555.12 2110.24,1555.12 2146.33,1519.02 2146.33,36.33 2130,20 45,20 20,45
GND on Top Solder "Top Solder-No Net" (solid): 45,725 665,725 695,695 695,190 695,170 680,155 675,150 60,150 55,150 35,170 35,715
GND on Top Solder "Top Solder-No Net" (solid): 85,1490 515,1490 570,1435 570,930 520,880 70,880 35,915 35,1440
no net on Top Solder "Top Solder-No Net" (solid): 975,855 1345,855 1355,855 1365,845 1365,370 1365,310 1340,285 1335,280 975,280 960,295 960,840
GND on Bottom Solder "Bottom Solder-No Net" (solid): 20,1540 30,1550 530,1550 690,1390 690,865 640,815 35,815 20,830
GND on Bottom Solder "Bottom Solder-No Net" (solid): 885,1550 1520,1550 1550,1520 1550,1140 1532.05,1122.05 889.76,1122.05 867.24,1122.05 846.46,1142.83 846.46,1511.46
GND on Bottom Solder "Bottom Layer-No Net" (solid): 1305,700 1375,630 1375,80 1315,20 35,20 21,34 21,656 65,700

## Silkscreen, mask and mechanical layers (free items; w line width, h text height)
Top Overlay:
  lines w5: 858.19,1535 858.19,1139.44 595.02,1139.44 595.02,1535 974.33,1535 1339.33,1535 1364.33,1535 ; 1364.33,1535 1329.33,1550 1329.33,1520 1364.33,1535
  lines w6: 1364.33,1315 1580,1315 1580,1550 1364.33,1550 1364.33,1315
  text "VIN" at 625,85 h30
  text "GND" at 1015,80 h30
  text "PMP40286" at 1810,70 h40
Top Solder:
  region: 726,55 726,157.52 824,157.52 824,55
  region: 896,55 896,157.52 994,157.52 994,55
Drill Guide:
  text ".Layer_Name" at 577,-858.49 h60
M1 Board Outline:
  the board outline again, w10
  text ".Layer_Name" at 577,-858.49 h60
M2 Board Dimensions:
  rectangle: 0,-275 125,-150
  rectangle: 125,-400 500,-275
  lines w7: 0,-275 1000,-275 ; 125,-400 125,-150 ; 250,-400 250,-150 ; 500,-400 500,-150 ; 750,-400 750,-150 ; 0,-400 1000,-400 1000,-150 0,-150 0,-400
  text ".Layer_Name" at 577,-858.49 h60
M3 3D STEP Top:
  text ".Layer_Name" at 577,-858.49 h60
M4 3D STEP Bottom:
  text ".Layer_Name" at 577,-858.49 h60
M5 Assembly Top:
  lines w10: -292,-930.17 6308,-930.17 ; -292,-726.83 6310,-726.83 ; -292,-523.5 -292,-1133.5 3713,-1133.5 6310,-1133.5 6310,-523.5 -291.5,-523.5 -291.5,-1133.5 1284,-1133.5 ; 2173,-1133.5 2173,-523.5 ; 3440,-726.83 3440,-523.5 ; 4280,-726.83 4280,-523.5 ; 4902,-1140 4902,-937.17
  text "COMPONENTS MARKED 'DNP' SHOULD NOT BE POPULATED." at 1153.5,-318.5 h60
  text "ASSEMBLY VARIANT:" at 1153,-434 h60
  text ".VariantName" at 2189,-434 h60
  text "PCB VIEWED FROM TOP SIDE" at -228.5,-655.67 h60
  text "BOARD #:" at 2248,-655.67 h60
  text ".PRJ_Number" at 2793.5,-655.67 h60
  text "REV:" at 3638,-655.67 h60
  text ".PCB_Rev" at 3929.5,-655.67 h60
  text "SVN REV:" at 4476,-655.67 h60
  text ".VersionControl_RevNumber" at 4982,-655.67 h60
  text "TID #:" at 2248,-859 h60
  text ".TID" at 2793.5,-859 h60
  text "PLOT NAME =" at -228.5,-1064.34 h60
  text ".plot_File_Name" at 577,-1064.34 h60
  text "GENERATED    :" at 2250,-1064.34 h60
  text ".Print_Date" at 3119.5,-1064.34 h60
  text ".Print_Time" at 3848.5,-1064.34 h60
  text "TEXAS INSTRUMENTS" at 5113,-1064.34 h60
M6 Assembly Bottom:
  lines w10: -292.5,-727.33 6309.5,-727.33 ; -290.5,-930.67 6309.5,-930.67 ; 1115.5,-1140.5 1115.5,-937.67 ; 1737.5,-727.33 1737.5,-524 ; 2577.5,-727.33 2577.5,-524 ; 3844.5,-1134 3844.5,-524 ; 4733.5,-1134 6309,-1134 6309,-524 -292.5,-524 -292.5,-1134 2304.5,-1134 6309.5,-1134 6309.5,-524
  text "COMPONENTS MARKED 'DNP' SHOULD NOT BE POPULATED." at 6102,-318 h60
  text ".VariantName" at 5058,-434 h60
  text "ASSEMBLY VARIANT:" at 6097,-434 h60
  text ".VersionControl_RevNumber" at 1035.5,-656.17 h60
  text "SVN REV:" at 1541.5,-656.17 h60
  text ".PCB_Rev" at 2088,-656.17 h60
  text "REV:" at 2379.5,-656.17 h60
  text ".PRJ_Number" at 3224,-656.17 h60
  text "BOARD #:" at 3769.5,-656.17 h60
  text "PCB VIEWED FROM BOTTOM SIDE" at 6246,-656.17 h60
  text ".TID" at 3224,-859.5 h60
  text "TID #:" at 3769.5,-859.5 h60
  text "TEXAS INSTRUMENTS" at 904.5,-1064.84 h60
  text ".Print_Time" at 2169,-1064.84 h60
  text ".Print_Date" at 2898,-1064.84 h60
  text "GENERATED    :" at 3767.5,-1064.84 h60
  text ".plot_File_Name" at 5440.5,-1064.84 h60
  text "PLOT NAME =" at 6246,-1064.84 h60
M9 Title Sheet:
  drawing of 57 lines, arcs and shapes, not listed
  text "1" at 739.84,8036.5 h70
  text "2" at 3235.5,8036.5 h70
  text "3" at 5724.84,8036.5 h70
  text "4" at 8231.51,8036.5 h70
  text "5" at 10730.5,8036.5 h70
  text "6" at 13235.5,8036.5 h70
  text "A" at -416.5,6893.5 h70
  text "A" at 14383.5,6893.5 h70
  text "B" at -416.5,4513.5 h70
  text "B" at 14383.5,4513.5 h70
  text "C" at -416.5,2138.5 h70
  text "C" at 14383.5,2138.5 h70
  text "PROJECT TITLE:" at 11343.5,277.5 h45
  text ".PRJ_Title" at 11393.5,144.17 h70
  text "DESIGNED FOR:" at 11343.5,-23.5 h45
  text ".PRJ_Customer" at 11393.5,-163.5 h70
  text "D" at -416.5,-231.5 h70
  text "D" at 14383.5,-231.5 h70
  text "FILE NAME:" at 11343.5,-323.5 h45
  text ".PCB_File_Name_No_Path" at 11393.5,-443.5 h70
  text "Texas Instruments (TI) and/or its licensors do not warrant the accuracy or completeness of this specification" at 6374,-605.34 h45
  text "ENGINEER:" at 11343.5,-613.5 h45
  text "LAYOUT BY:" at 12848.5,-613.5 h45
  text "or any information contained therein. TI and/or its licensors do not warrant that this design will meet" at 6329.01,-718 h45
  text ".PRJ_Engineer" at 11393.5,-768.49 h70
  text ".PCB_Layout" at 12899,-768.49 h70
  text "the specifications, will be suitable for your application or fit for any particular purpose, or will operate in" at 6329.01,-830.67 h45
  text ".Layer_Name" at 577,-858.49 h60
  text "ALTIUM DESIGNER VERSION:" at 12848.5,-923.5 h45
  text "an implementation. TI and/or its licensors do not warrant that the design is production worthy. You should" at 6329.01,-943.33 h45
  text "completely validate and test your design implementation to confirm the system functionality for your application." at 6374,-1056 h45
  text ".print_Scale" at 11393.5,-1056.83 h70
  text ".Application_BuildNumber" at 12899,-1056.83 h70
  text "1" at 739.84,-1263.5 h70
  text "2" at 3235.5,-1263.5 h70
  text "3" at 5724.84,-1263.5 h70
  text "4" at 8231.51,-1263.5 h70
  text "5" at 10730.5,-1263.5 h70
  text "6" at 13235.5,-1263.5 h70
M10 Fab Notes:
  drawing of 173 lines, arcs and shapes, not listed
  text "DESIGN INFORMATION" at 12377.02,6201 h60
  text "MIN. TRACK WIDTH:" at 11732.46,6021 h60
  text "8" at 12828.7,6021 h60
  text "MIL" at 12983.46,6021 h60
  text "MIN. CLEARANCE:" at 11732.46,5889 h60
  text "0.2" at 12768.7,5889 h60
  text "mm" at 12983.46,5889 h60
  text "MIN. VIA PAD SIZE:" at 11732.46,5757 h60
  text "24" at 12798.71,5757 h60
  text "MIL" at 12983.46,5757 h60
  text "0.05mm (2MIL)" at 12427.46,5615.29 h60
  text "MINIMUM ANNULAR RING" at 11403.23,5611 h60
  text "EXTERNAL" at 13135.46,5611 h60
  text "PER" at 11603.23,5493 h60
  text "IPC-D-275 CLASS 2 LEVEL C" at 11823.23,5493 h60
  text "MIL, HOLES" at 13311.46,5380.71 h60
  text "+/-" at 12919,5380 h60
  text "+/-" at 13773,5380 h60
  text "REGISTRATION TOLERANCES:" at 11403.23,5375 h60
  text "METAL" at 12603,5375 h60
  text "5" at 13179.2,5375 h60
  text "3" at 14012.2,5375 h60
  text "MIL" at 14128.46,5375 h60
  text "+/-" at 13773,5262 h60
  text "HOLE SIZE TOLERANCE (UNLESS OTHERWISE SPECIFIED):" at 11403.23,5257 h60
  text "3" at 14012.2,5257 h60
  text "MIL" at 14128.46,5257 h60
  text "MATERIAL:" at 11328.46,5047.54 h60
  text "FR-4 High Tg" at 12314.9,4907.21 h60
  text "FR-408" at 11749.46,4898.64 h60
  text "OTHER" at 13237.46,4898.64 h60
  text "X" at 12160,4895 h60
  text "62 MIL (1.6mm) +/-10%" at 12069.56,4735.92 h60
  text "THICKNESS:" at 11403.23,4731.64 h60
  text "X" at 11941.4,4731.64 h60
  text "OTHER" at 13354.46,4731.64 h60
  text "TOLERANCE:" at 11403.23,4573.64 h60
  text "X" at 12242.53,4573.64 h60
  text "ANSI IPC-6012 TYPE 3 CLASS 2" at 12429.48,4573.64 h60
  text "OTHER +/-" at 12429.46,4417.64 h60
  text "BOW & TWIST:" at 11403.23,4260.64 h60
  text "X" at 12242.53,4260.64 h60
  text "ANSI IPC-6012 TYPE 3 CLASS 2" at 12429.48,4260.64 h60
  text "OTHER +/-" at 12429.46,4102.13 h60
  text "DRILLING:" at 11328.46,3963.64 h60
  text "REFERENCE:" at 11403.23,3846.64 h60
  text "X" at 12051.46,3846.64 h60
  text "AS SHOWN" at 12238.46,3846.64 h60
  text "X" at 12952.46,3846.64 h60
  text "NC_DRILL FILES" at 13089.46,3846.64 h60
  text "PTH MIN COPPER THICKNESS:" at 11403.23,3688.64 h60
  text "X" at 12753.46,3688.64 h60
  text "1MIL" at 12890.46,3688.64 h60
  text "OTHER" at 13387.46,3688.64 h60
  text "BOARD FINISH:" at 11328.46,3529.64 h60
  text "SILKSCREEN:" at 11483.68,3411.64 h60
  text "X" at 12432.46,3411.64 h60
  text "TOP" at 12558.46,3411.64 h60
  text "X" at 12942.46,3411.64 h60
  text "BOTTOM" at 13069.46,3411.64 h60
  text "SILKSCREEN COLOR:" at 11483.68,3244.64 h60
  text "X" at 12431.42,3244.64 h60
  text "WHITE" at 12558.46,3244.64 h60
  text "OTHER" at 13069.46,3244.64 h60
  text "X" at 12562.42,3085.44 h60
  text "GREEN" at 12689.46,3085.44 h60
  text "OTHER" at 13307.46,3085.44 h60
  text "SOLDER RESIST COLOR:" at 11483.68,3074.64 h60
  text "X" at 12562.42,2915.44 h60
  text "MATTE" at 12689.46,2915.44 h60
  text "SEMI-GLOSS" at 13307,2914.8 h60
  text "IMMERSION GOLD (ENIG)" at 12389.46,2726.92 h60
  text "ENEPIG" at 13727,2723.64 h60
  text "SURFACE FINISH:" at 11328.46,2722.64 h60
  text "X" at 12202.51,2722.64 h60
  text "IMM. TIN/SILVER OR EQUIV" at 11658,2565.64 h60
  text "OTHER" at 13089.46,2565.64 h60
  text "ARRAY/PANEL:" at 11328.46,2386.64 h60
  text "CUT AND TRIM PER M1 BOARD OUTLINE" at 12389.46,2382.35 h60
  text "N.C. ROUTE" at 12389.46,2230.64 h60
  text "X" at 13068.46,2230.64 h60
  text "V. SCORE" at 13255.46,2230.64 h60
  text "CERTIFICATION:" at 11328.46,2093.64 h60
  text "MATERIALS AND WORKMANSHIP FOR ALL PCBS" at 12053.46,2093.64 h60
  text "TO MEET OR EXCEED THE REQUIREMENTS OF:" at 12053.46,1995.64 h60
  text "X" at 11679.96,1859.13 h60
  text "ANSI IPC-A-600F CLASS ->" at 11818.96,1859.13 h60
  text "X" at 13458.02,1859.13 h60
  text "2" at 13576.96,1859.14 h60
  text "1" at 13261.96,1857.64 h60
  text "3" at 13930.96,1857.64 h60
  text "X" at 12494.02,1699.64 h60
  text "RoHS" at 12630.96,1699.64 h60
  text "OTHER" at 13275.36,1699.64 h60
  text "PER ORDER" at 13672.42,1699.64 h60
  text "ALL BOARDS MUST MEET OR EXCEED UL94-V0 REQUIREMENTS." at 11356,1534 h60
  text "PCB MUST BEAR THE UL94V-0 UL REGISTERED MATERIAL ID NUMBER" at 11356,1414 h60
  text "ADDITIONAL REQUIREMENTS:" at 11328.46,1240.64 h60
  text "MICROSECTION:" at 11403.23,1125.64 h60
  text "YES" at 12308.96,1125.64 h60
  text "REQUIRED" at 13170.46,969.49 h60
  text "BARE BOARD ELEC. TEST:" at 11403.23,966.64 h60
  text "NONE" at 12708.96,966.64 h60
  text "X" at 13043.46,966.64 h60
  text "PER ORDER" at 13762.46,966.64 h60
  text ".Layer_Name" at 577,-858.49 h60
M11 Gerber Information:
  lines w10: -292,-930.17 6308,-930.17 ; -292,-726.83 6310,-726.83 ; -292,-523.5 -292,-1133.5 3713,-1133.5 6310,-1133.5 6310,-523.5 -291.5,-523.5 -291.5,-1133.5 1284,-1133.5 ; 2173,-1133.5 2173,-523.5 ; 3440,-726.83 3440,-523.5 ; 4280,-726.83 4280,-523.5 ; 4902,-1140 4902,-937.17
  text "ALL ARTWORK VIEWED FROM TOP SIDE" at -228.5,-655.67 h60
  text "BOARD #:" at 2248,-655.67 h60
  text ".PRJ_Number" at 2793.5,-655.67 h60
  text "REV:" at 3638,-655.67 h60
  text ".PCB_Rev" at 3929.5,-655.67 h60
  text "SVN REV:" at 4476,-655.67 h60
  text ".VersionControl_RevNumber" at 4982,-655.67 h60
  text "LAYER NAME =" at -228.5,-858.49 h60
  text "TID #:" at 2248,-859 h60
  text ".TID" at 2793.5,-859 h60
  text "PLOT NAME =" at -228.5,-1064.34 h60
  text ".plot_File_Name" at 577,-1064.34 h60
  text "GENERATED    :" at 2250,-1064.34 h60
  text ".Print_Date" at 3119.5,-1064.34 h60
  text ".Print_Time" at 3848.5,-1064.34 h60
  text "TEXAS INSTRUMENTS" at 5113,-1064.34 h60
M12 Stackup:
  drawing of 295 lines, arcs and shapes, not listed
  text "Layer" at 9790.58,7830 h60
  text "Name" at 10200.49,7830 h60
  text "Material" at 11140.23,7830 h60
  text "Thickness" at 12000,7830 h60
  text "Constant" at 12649.83,7830 h60
  text "Board Layer Stack" at 13219.69,7830 h60
  text "1" at 9790.58,7710 h60
  text "Top Overlay" at 10200.49,7710 h60
  text "2" at 9790.58,7590 h60
  text "Top Solder" at 10200.49,7590 h60
  text "Solder Resist" at 11140.23,7590 h60
  text "0.40mil" at 12000,7590 h60
  text "3.5" at 12649.83,7590 h60
  text "3" at 9790.58,7470 h60
  text "Top Layer" at 10200.49,7470 h60
  text "Copper" at 11140.23,7470 h60
  text "1.40mil" at 12000,7470 h60
  text "4" at 9790.58,7350 h60
  text "Dielectric1" at 10200.49,7350 h60
  text "FR-4" at 11140.23,7350 h60
  text "59.20mil" at 12000,7350 h60
  text "4.8" at 12649.83,7350 h60
  text "5" at 9790.58,7230 h60
  text "Signal Layer 1" at 10200.49,7230 h60
  text "Copper" at 11140.23,7230 h60
  text "1.42mil" at 12000,7230 h60
  text "6" at 9790.58,7110 h60
  text "Dielectric 3" at 10200.49,7110 h60
  text "5.00mil" at 12000,7110 h60
  text "4.2" at 12649.83,7110 h60
  text "7" at 9790.58,6990 h60
  text "Signal Layer 2" at 10200.49,6990 h60
  text "Copper" at 11140.23,6990 h60
  text "1.42mil" at 12000,6990 h60
  text "8" at 9790.58,6870 h60
  text "Dielectric 2" at 10200.49,6870 h60
  text "10.00mil" at 12000,6870 h60
  text "4.2" at 12649.83,6870 h60
  text "9" at 9790.58,6750 h60
  text "Bottom Layer" at 10200.49,6750 h60
  text "Copper" at 11140.23,6750 h60
  text "1.40mil" at 12000,6750 h60
  text "10" at 9790.58,6630 h60
  text "Bottom Solder" at 10200.49,6630 h60
  text "Solder Resist" at 11140.23,6630 h60
  text "0.40mil" at 12000,6630 h60
  text "3.5" at 12649.83,6630 h60
  text "11" at 9790.58,6510 h60
  text "Bottom Overlay" at 10200.49,6510 h60
  text ".Layer_Name" at 577,-858.49 h60
M13 Component Bodies Top:
  text ".Layer_Name" at 577,-858.49 h60
M14 Component Bodies Bottom:
  text ".Layer_Name" at 577,-858.49 h60
M15 Courtyards Top:
  text ".Layer_Name" at 577,-858.49 h60
M16 Courtyards Bottom:
  text ".Layer_Name" at 577,-858.49 h60
Drill Drawing:
  circle w10: c5548.9,3308.1 r22.14
  circle w10: c5548.9,3208.48 r13.28
  circle w10: c5548.9,3208.48 r22.14
  lines w10: 5526.76,2212.26 5548.9,2190.12 5571.04,2212.26 5548.9,2234.39 5526.76,2212.26 ; 5526.76,2334.02 5571.04,2334.02 5548.9,2289.74 5526.76,2334.02 ; 5526.76,2389.36 5571.04,2389.36 5571.04,2433.64 5526.76,2433.64 5526.76,2389.36 ; 5526.76,2500.05 5537.83,2500.05 5537.83,2488.98 5559.97,2488.98 5559.97,2500.05 5571.04,2500.05 5571.04,2522.19 5559.97,2522.19 5559.97,2533.26 5537.83,2533.26 5537.83,2522.19 5526.76,2522.19 5526.76,2500.05 ; 5526.76,2588.61 5548.9,2599.68 5571.04,2588.61 5559.97,2610.75 5571.04,2632.88 5548.9,2621.81 5526.76,2632.88 5537.83,2610.75 5526.76,2588.61 ; 5526.76,2699.3 5537.83,2699.3 5548.9,2688.23 5559.97,2699.3 5571.04,2699.3 5559.97,2710.37 5571.04,2721.44 5559.97,2721.44 5548.9,2732.51 5537.83,2721.44 5526.76,2721.44 5537.83,2710.37 5526.76,2699.3 ; 5526.76,2787.85 5571.04,2787.85 5571.04,2832.13 5526.76,2832.13 5526.76,2787.85 ; 5526.76,2887.47 5526.76,2898.54 5537.83,2909.61 5526.76,2920.68 5526.76,2931.75 5537.83,2931.75 5548.9,2920.68 5559.97,2931.75 5571.04,2931.75 5571.04,2920.68 5559.97,2909.61 5571.04,2898.54 5571.04,2887.47 5559.97,2887.47 5548.9,2898.54 5537.83,2887.47 5526.76,2887.47 ; 5526.76,2998.17 5537.83,2998.17 5548.9,2987.1 5559.97,2998.17 5571.04,2998.17 5559.97,3009.23 5571.04,3020.3 5559.97,3020.3 5548.9,3031.37 5537.83,3020.3 5526.76,3020.3 5537.83,3009.23 5526.76,2998.17 ; 5526.76,3131 5571.04,3131 5548.9,3086.72 5526.76,3131 ; 5535.62,2325.16 5562.18,2325.16 5548.9,2298.6 5535.62,2325.16 ; 5535.62,2398.22 5562.18,2398.22 5562.18,2424.78 5535.62,2424.78 5535.62,2398.22 ; 5535.62,2703.73 5542.26,2703.73 5548.9,2697.08 5555.54,2703.73 5562.18,2703.73 5555.54,2710.37 5562.18,2717.01 5555.54,2717.01 5548.9,2723.65 5542.26,2717.01 5535.62,2717.01 5542.26,2710.37 5535.62,2703.73
  lines w12: 5486,2160.23 7375.11,2160.23 ; 5486,3355.7 7375.11,3355.7 ; 5801.63,2060.61 5801.63,3455.32 ; 6118.82,2060.61 6118.82,3455.32 ; 6740.56,2060.61 6740.56,3455.32 ; 6984.88,2060.61 6984.88,3455.32 ; 5486,2060.61 7375.11,2060.61 7375.11,3455.32 5486,3455.32 5486,2060.61
  text "Symbol" at 5545.77,3385.59 h72
  text "Quantity" at 5831.52,3385.59 h72
  text "Finished Hole Size" at 6148.7,3385.59 h72
  text "Plated" at 6770.45,3385.59 h72
  text "Hole Type" at 7014.77,3385.59 h72
  text "7" at 5831.52,3285.96 h60
  text "6.00mil (0.152mm)" at 6148.7,3285.96 h60
  text "PTH" at 6770.45,3285.96 h60
  text "Round" at 7014.77,3285.96 h60
  text "11" at 5831.52,3186.34 h60
  text "7.87mil (0.200mm)" at 6148.7,3186.34 h60
  text "PTH" at 6770.45,3186.34 h60
  text "Round" at 7014.77,3186.34 h60
  text "2" at 5831.52,3086.72 h60
  text "8.00mil (0.203mm)" at 6148.7,3086.72 h60
  text "PTH" at 6770.45,3086.72 h60
  text "Round" at 7014.77,3086.72 h60
  text "4" at 5831.52,2987.1 h60
  text "10.00mil (0.254mm)" at 6148.7,2987.1 h60
  text "PTH" at 6770.45,2987.1 h60
  text "Round" at 7014.77,2987.1 h60
  text "167" at 5831.52,2887.47 h60
  text "11.81mil (0.300mm)" at 6148.7,2887.47 h60
  text "PTH" at 6770.45,2887.47 h60
  text "Round" at 7014.77,2887.47 h60
  text "24" at 5831.52,2787.85 h60
  text "12.00mil (0.305mm)" at 6148.7,2787.85 h60
  text "PTH" at 6770.45,2787.85 h60
  text "Round" at 7014.77,2787.85 h60
  text "14" at 5831.52,2688.23 h60
  text "15.75mil (0.400mm)" at 6148.7,2688.23 h60
  text "PTH" at 6770.45,2688.23 h60
  text "Round" at 7014.77,2688.23 h60
  text "19" at 5831.52,2588.61 h60
  text "16.00mil (0.406mm)" at 6148.7,2588.61 h60
  text "PTH" at 6770.45,2588.61 h60
  text "Round" at 7014.77,2588.61 h60
  text "6" at 5831.52,2488.98 h60
  text "20.00mil (0.508mm)" at 6148.7,2488.98 h60
  text "PTH" at 6770.45,2488.98 h60
  text "Round" at 7014.77,2488.98 h60
  text "4" at 5831.52,2389.36 h60
  text "37.00mil (0.940mm)" at 6148.7,2389.36 h60
  text "PTH" at 6770.45,2389.36 h60
  text "Round" at 7014.77,2389.36 h60
  text "4" at 5831.52,2289.74 h60
  text "23.62mil (0.600mm)" at 6148.7,2289.74 h60
  text "PTH" at 6770.45,2289.74 h60
  text "Slot" at 7014.77,2289.74 h60
  text "2" at 5831.52,2190.12 h60
  text "23.62mil (0.600mm)" at 6148.7,2190.12 h60
  text "PTH" at 6770.45,2190.12 h60
  text "Slot" at 7014.77,2190.12 h60
  text "264 Total" at 5831.52,2090.5 h60
  text "Slot definitions :" at 5545.77,2010.88 h60
  text "Routed Path Length" at 5989.08,2010.88 h60
  text "= Calculated from tool start centre position to tool end centre position." at 6521.41,2010.88 h60
  text "Hole Length" at 5989.08,1961.15 h60
  text "= Routed Path Length + Tool Size = Slot length as defined in the PCB layout" at 6321.61,1961.15 h60
  text ".Layer_Name" at 577,-858.49 h60

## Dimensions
2165.35,0 to 0,0 on M2 Board Dimensions
0,-400 to 1000,-400 on M2 Board Dimensions
0,0 to 0,1574.8 on M2 Board Dimensions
